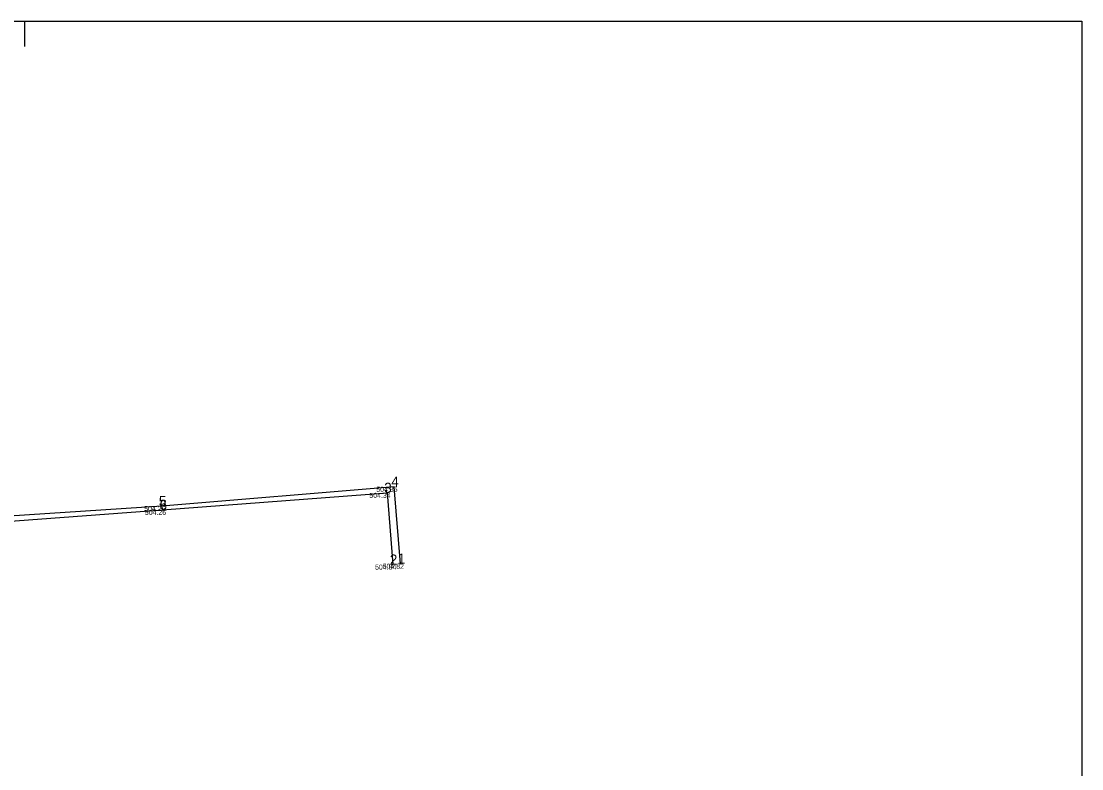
# Model space of a CAD drawing. Extents: x -873642.4 to -873558.4, y -1012603.5 to -1012544.1.
# Drawn here: x -873600.57 to -873558.45, y -1012573.76 to -1012544.06 of the extents above; entities that cross this region are included whole.
import ezdxf

# ---------------------------------------------------------------- set-up
doc = ezdxf.new("R2010")
doc.units = 0
for name, color, linetype in [('Měřený bod', 7, 'Continuous'), ('rám', 7, 'Continuous'), ('teplovod', 7, 'Continuous'), ('Výška měřeného bodu', 7, 'Continuous'), ('Číslo měřeného bodu', 7, 'Continuous')]:
    doc.layers.add(name, color=color, linetype=linetype)

msp = doc.modelspace()

# ---------------------------------------------------------------- linework, layer by layer
at = {"layer": 'Měřený bod'}
for p, q in [((-873585.76, -1012562.556), (-873585.76, -1012562.556)), ((-873586.039, -1012562.797), (-873586.039, -1012562.797)), ((-873594.984, -1012563.323), (-873594.984, -1012563.323)), ((-873594.957, -1012563.474), (-873594.957, -1012563.474)), ((-873585.815, -1012565.648), (-873585.815, -1012565.648)), ((-873585.514, -1012565.613), (-873585.514, -1012565.613))]:
    msp.add_line(p, q, dxfattribs=at)
at = {"layer": 'rám'}
msp.add_line((-873600.449, -1012544.06), (-873600.449, -1012545.06), dxfattribs=at)
msp.add_lwpolyline([(-873642.449, -1012603.46), (-873642.449, -1012544.06), (-873558.449, -1012544.06), (-873558.449, -1012603.46)], close=True, dxfattribs=at)
at = {"layer": 'teplovod'}
for points in [[(-873585.514, -1012565.613), (-873585.76, -1012562.556), (-873594.984, -1012563.323), (-873606.523, -1012564.081), (-873614.709, -1012564.674), (-873614.845, -1012562.721), (-873616.845, -1012562.879), (-873616.617, -1012564.885), (-873619.591, -1012565.185), (-873620.816, -1012565.342), (-873622.675, -1012565.585), (-873624.155, -1012565.35), (-873626.267, -1012564.948), (-873627.175, -1012564.831)], [(-873606.513, -1012564.331), (-873594.957, -1012563.474), (-873586.039, -1012562.797), (-873585.815, -1012565.648)]]:
    msp.add_lwpolyline(points, dxfattribs=at)

# ---------------------------------------------------------------- texts
at = {"layer": 'Výška měřeného bodu'}
for s, p in [('504.35', (-873586.471, -1012562.756)), ('504.34', (-873586.745, -1012562.997)), ('504.26', (-873595.692, -1012563.523)), ('504.26', (-873595.665, -1012563.674)), ('504.84', (-873586.521, -1012565.848)), ('504.82', (-873586.218, -1012565.813))]:
    msp.add_text(s, height=0.2, dxfattribs=at).set_placement(p)
at = {"layer": 'Číslo měřeného bodu'}
for s, p in [('4', (-873585.879, -1012562.556)), ('3', (-873586.155, -1012562.797)), ('5', (-873595.109, -1012563.323)), ('6', (-873595.078, -1012563.474)), ('2', (-873585.933, -1012565.648)), ('1', (-873585.617, -1012565.613))]:
    msp.add_text(s, height=0.4, dxfattribs=at).set_placement(p)

doc.saveas('drawing.dxf')
